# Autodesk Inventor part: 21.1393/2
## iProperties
Created: 2006-12
Part Number: 21.1393/2
Document SubType Name: Modeling
Designer: Andy Moles
Material: Steel
Density: 7.85 g/cm^3
Mass: 13.5725 g
Surface Area: 18.0778 cm^2
Volume: 1.72898 cm^3
Vendor: S
Description: POWER-LOCK BODY
Author: Andy Moles
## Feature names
1. Extrusion1
2. Extrusion2
3. Mirror1
4. Extrusion3
5. Extrusion4
6. Extrusion5
